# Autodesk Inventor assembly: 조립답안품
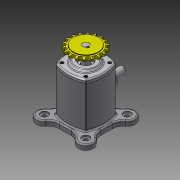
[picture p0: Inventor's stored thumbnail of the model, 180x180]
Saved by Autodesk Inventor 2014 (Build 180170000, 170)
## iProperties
Created: 2016-05
Part Number: 조립답안품
Document SubType Name: Assembly
Designer: Administrator
Author: Administrator
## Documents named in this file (11)
- C:\Users\Administrator\Desktop\460507V1016\조립답안품.iam
- C:\Users\Administrator\Desktop\460507V1016\본체1.ipt
- C:\Users\Administrator\Desktop\460507V1016\M4x0.7x12.ipt
- C:\Users\Administrator\Desktop\460507V1016\베어링-6203.ipt
- C:\Users\Administrator\Desktop\460507V1016\부시.ipt
- C:\Users\Administrator\Desktop\460507V1016\스프로킷.ipt
- C:\Users\Administrator\Desktop\460507V1016\슬라이더.ipt
- C:\Users\Administrator\Desktop\460507V1016\오일실.ipt
- C:\Users\Administrator\Desktop\460507V1016\커버.ipt
- C:\Users\Administrator\Desktop\460507V1016\키5x5.ipt
- C:\Users\Administrator\Desktop\460507V1016\편심축.ipt
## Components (8 placed, 1 different names)
1. M4x0.7x12:2
2. M4x0.7x12:3
3. M4x0.7x12:4
4. M4x0.7x12:5
5. M4x0.7x12:1
6. M4x0.7x12:6
7. M4x0.7x12:7
8. M4x0.7x12:8
